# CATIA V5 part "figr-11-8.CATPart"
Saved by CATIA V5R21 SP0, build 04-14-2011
Part number: Part1
Bounding box of the stored display mesh (mm): x -50 to 50, y -39.834 to 41.856, z -25 to 25
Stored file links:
  D:\CATIA V5R21 E-RESOURCES\CATIA-V5R21\catia-v5r21-prt\c11-catia-v5r21-prt\c11-catia-v5r21-figr-11-8.CATPart
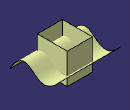
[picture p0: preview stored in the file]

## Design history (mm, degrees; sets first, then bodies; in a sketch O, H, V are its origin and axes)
Set1
  Sketch1 on yz-plane, origin (0, 0, 0), H (0, 1, 0), V (0, 0, 1)
    spline S1 through (-39.8338, -18.0686) (-4.7892, 0) (1.9431, -5.3632) (41.8556, 3.6938)
    point P1 (-4.7892, 0)
    coincidence: P1 H
  Extrude1: Element1 Sketch1, Lim1 50, Lim2 50, Direction yz-plane
  Sketch2 on xy-plane, origin (0, 0, 0), H (1, 0, 0), V (0, 1, 0)
    line L1 (-20.1634, 25.5896) -> (20.7534, 25.5896)
    line L2 (20.7534, 25.5896) -> (20.7534, -23.3463)
    line L3 (20.7534, -23.3463) -> (-20.1634, -23.3463)
    line L4 (-20.1634, -23.3463) -> (-20.1634, 25.5896)
    horizontal: L1 H, L3 H
    vertical: L2 V, L4 V
  Extrude2: Element1 Sketch2, Lim1 25, Lim2 25, Direction xy-plane
Body1 (main body)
